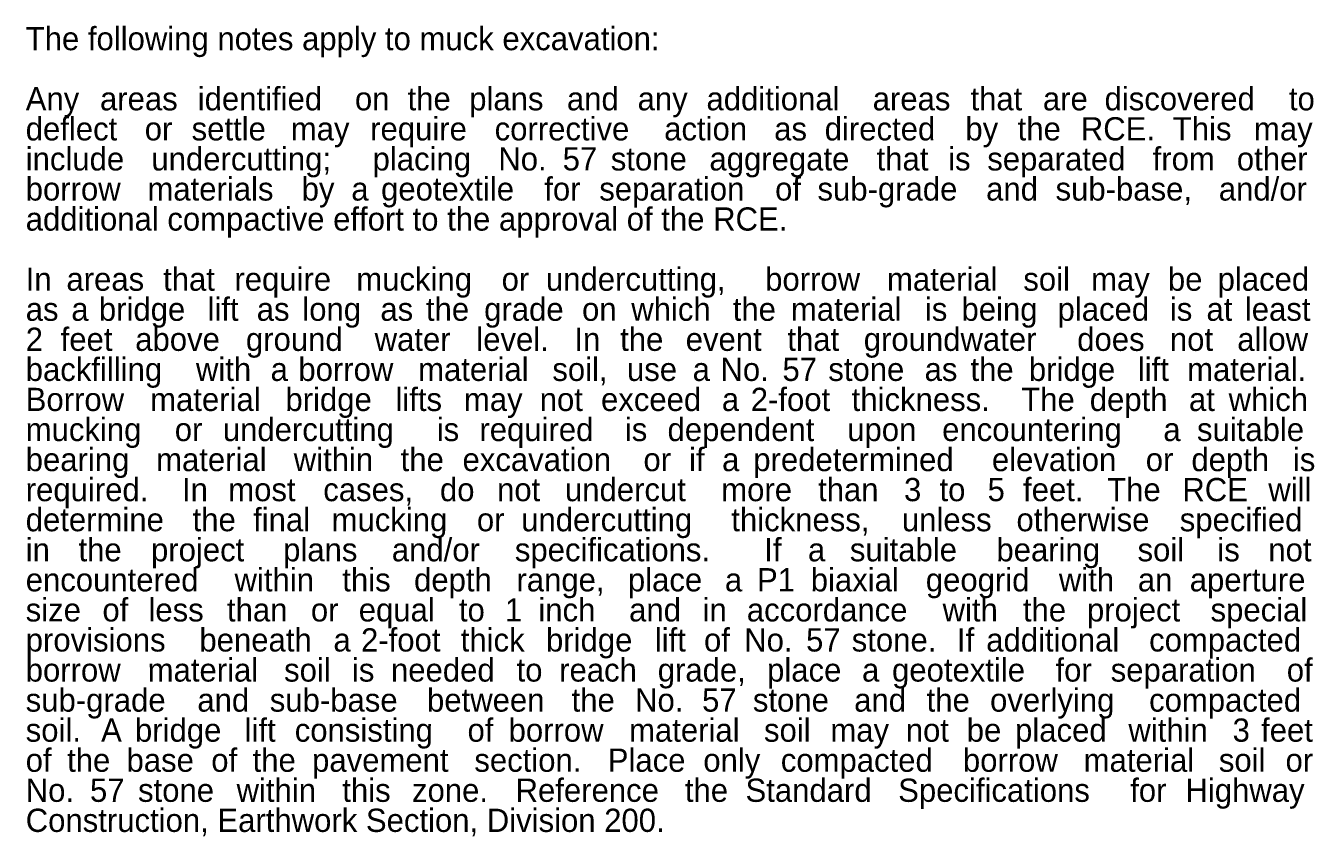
# Model space of a CAD drawing. Extents: x 4804 to 5434, y 4929 to 5221.
# Drawn here: x 5363.1 to 5432.9, y 5158.8 to 5202.8 of the extents above; entities that cross this region are included whole.
import ezdxf

# ---------------------------------------------------------------- set-up
doc = ezdxf.new("R2010")
doc.units = 0
doc.layers.add('RD_TX_RoadID', color=7, linetype='Continuous')

msp = doc.modelspace()

# ---------------------------------------------------------------- texts
at = {"layer": 'RD_TX_RoadID'}
for s, height, p in [('The following notes apply to muck excavation:', 1.25864, (5363.131, 5201.428)), ('Any ', 1.2586, (5363.131, 5198.17)), ('identified ', 1.25864, (5372.45, 5198.17)), ('the ', 1.2586, (5383.817, 5198.17)), ('plans ', 1.2586, (5387.155, 5198.17)), ('and ', 1.2586, (5392.449, 5198.17)), ('additional ', 1.25864, (5400.009, 5198.17)), ('that ', 1.2586, (5414.309, 5198.17)), ('discovered ', 1.25864, (5421.574, 5198.17)), ('to ', 1.2586, (5431.559, 5198.17)), ('areas ', 1.2586, (5367.155, 5198.17)), ('on ', 1.2586, (5380.966, 5198.17)), ('any ', 1.2586, (5396.278, 5198.17)), ('areas ', 1.2586, (5409.013, 5198.17)), ('are ', 1.2586, (5418.233, 5198.17)), ('deflect ', 1.2586, (5363.131, 5196.541)), ('settle ', 1.2586, (5372.118, 5196.541)), ('require ', 1.2586, (5381.791, 5196.541)), ('corrective ', 1.25864, (5388.533, 5196.541)), ('action ', 1.2586, (5397.718, 5196.541)), ('directed ', 1.2586, (5406.413, 5196.541)), ('by ', 1.2586, (5414.034, 5196.541)), ('the ', 1.2586, (5416.867, 5196.541)), ('RCE. ', 1.2586, (5420.286, 5196.541)), ('This ', 1.2586, (5425.269, 5196.541)), ('or ', 1.2586, (5369.578, 5196.541)), ('may ', 1.2586, (5377.491, 5196.541)), ('as ', 1.2586, (5403.677, 5196.541)), ('may ', 1.2586, (5429.666, 5196.541)), ('include ', 1.2586, (5363.131, 5194.912)), ('undercutting; ', 1.25864, (5369.939, 5194.912)), ('placing ', 1.2586, (5381.922, 5194.912)), ('No. ', 1.2586, (5388.731, 5194.912)), ('57 ', 1.2586, (5392.217, 5194.912)), ('stone ', 1.2586, (5394.825, 5194.912)), ('aggregate ', 1.2586, (5400.168, 5194.912)), ('that ', 1.2586, (5409.224, 5194.912)), ('is ', 1.2586, (5413.1, 5194.912)), ('separated ', 1.2586, (5415.219, 5194.912)), ('from ', 1.2586, (5424.178, 5194.912)), ('other ', 1.2586, (5428.739, 5194.912)), ('borrow ', 1.2586, (5363.131, 5193.283)), ('materials ', 1.2586, (5369.725, 5193.283)), ('by ', 1.2586, (5378.08, 5193.283)), ('geotextile ', 1.25864, (5382.381, 5193.283)), ('for ', 1.2586, (5391.222, 5193.283)), ('separation ', 1.25864, (5394.201, 5193.283)), ('of ', 1.2586, (5403.727, 5193.283)), ('sub-grade ', 1.2586, (5406.022, 5193.283)), ('and ', 1.2586, (5415.157, 5193.283)), ('sub-base, ', 1.2586, (5418.919, 5193.283)), ('and/or ', 1.2586, (5427.761, 5193.283)), ('a ', 1.2586, (5380.768, 5193.283)), ('additional compactive effort to the approval of the RCE. ', 1.25864, (5363.131, 5191.654)), ('In ', 1.2586, (5363.131, 5188.396)), ('that ', 1.2586, (5370.572, 5188.396)), ('require ', 1.2586, (5374.436, 5188.396)), ('mucking ', 1.2586, (5381.039, 5188.396)), ('undercutting, ', 1.25864, (5391.312, 5188.396)), ('borrow ', 1.2586, (5403.187, 5188.396)), ('material ', 1.2586, (5409.788, 5188.396)), ('soil ', 1.2586, (5417.172, 5188.396)), ('be ', 1.2586, (5425.004, 5188.396)), ('placed ', 1.2586, (5427.698, 5188.396)), ('areas ', 1.2586, (5365.336, 5188.396)), ('or ', 1.2586, (5388.911, 5188.396)), ('may ', 1.2586, (5420.843, 5188.396)), ('bridge ', 1.2586, (5367.094, 5186.767)), ('lift ', 1.2586, (5372.983, 5186.767)), ('long ', 1.2586, (5378.115, 5186.767)), ('the ', 1.2586, (5384.813, 5186.767)), ('grade ', 1.2586, (5387.966, 5186.767)), ('which ', 1.2586, (5395.933, 5186.767)), ('the ', 1.2586, (5401.431, 5186.767)), ('material ', 1.2586, (5404.584, 5186.767)), ('is ', 1.2586, (5411.841, 5186.767)), ('being ', 1.2586, (5413.823, 5186.767)), ('placed ', 1.2586, (5419.027, 5186.767)), ('is ', 1.2586, (5425.112, 5186.767)), ('least ', 1.2586, (5429.172, 5186.767)), ('as ', 1.2586, (5363.131, 5186.767)), ('a ', 1.2586, (5365.601, 5186.767)), ('as ', 1.2586, (5375.645, 5186.767)), ('as ', 1.2586, (5382.342, 5186.767)), ('on ', 1.2586, (5393.269, 5186.767)), ('at ', 1.2586, (5427.094, 5186.767)), ('2 ', 1.2586, (5363.131, 5185.138)), ('feet ', 1.2586, (5365.024, 5185.138)), ('above ', 1.2586, (5369.064, 5185.138)), ('ground ', 1.2586, (5375.061, 5185.138)), ('water ', 1.2586, (5382.033, 5185.138)), ('level. ', 1.2586, (5387.54, 5185.138)), ('In ', 1.2586, (5392.853, 5185.138)), ('the ', 1.2586, (5395.331, 5185.138)), ('event ', 1.2586, (5398.883, 5185.138)), ('that ', 1.2586, (5404.391, 5185.138)), ('groundwater ', 1.25864, (5408.529, 5185.138)), ('does ', 1.2586, (5420.092, 5185.138)), ('not ', 1.2586, (5425.112, 5185.138)), ('allow ', 1.2586, (5428.761, 5185.138)), ('backfilling ', 1.25864, (5363.131, 5183.509)), ('with ', 1.2586, (5372.353, 5183.509)), ('borrow ', 1.2586, (5377.901, 5183.509)), ('material ', 1.2586, (5384.388, 5183.509)), ('soil, ', 1.2586, (5391.658, 5183.509)), ('No. ', 1.2586, (5400.765, 5183.509)), ('57 ', 1.2586, (5404.125, 5183.509)), ('stone ', 1.2586, (5406.608, 5183.509)), ('the ', 1.2586, (5414.307, 5183.509)), ('bridge ', 1.2586, (5417.472, 5183.509)), ('lift ', 1.2586, (5423.373, 5183.509)), ('material. ', 1.2586, (5426.047, 5183.509)), ('a ', 1.2586, (5376.396, 5183.509)), ('use ', 1.2586, (5395.702, 5183.509)), ('a ', 1.2586, (5399.259, 5183.509)), ('as ', 1.2586, (5411.824, 5183.509)), ('Borrow ', 1.2586, (5363.131, 5181.88)), ('material ', 1.2586, (5369.872, 5181.88)), ('bridge ', 1.2586, (5377.2, 5181.88)), ('lifts ', 1.2586, (5383.159, 5181.88)), ('exceed ', 1.2586, (5394.295, 5181.88)), ('2-foot ', 1.2586, (5402.407, 5181.88)), ('thickness. ', 1.25864, (5407.875, 5181.88)), ('The ', 1.2586, (5417.059, 5181.88)), ('depth ', 1.2586, (5420.772, 5181.88)), ('which ', 1.2586, (5428.293, 5181.88)), ('may ', 1.2586, (5386.87, 5181.88)), ('not ', 1.2586, (5390.975, 5181.88)), ('a ', 1.2586, (5400.843, 5181.88)), ('at ', 1.2586, (5426.144, 5181.88)), ('mucking ', 1.2586, (5363.131, 5180.251)), ('or ', 1.2586, (5371.206, 5180.251)), ('undercutting ', 1.25864, (5373.809, 5180.251)), ('is ', 1.2586, (5385.398, 5180.251)), ('required ', 1.2586, (5387.708, 5180.251)), ('is ', 1.2586, (5395.588, 5180.251)), ('dependent ', 1.2586, (5397.898, 5180.251)), ('upon ', 1.2586, (5407.633, 5180.251)), ('encountering ', 1.25864, (5412.775, 5180.251)), ('a ', 1.2586, (5424.756, 5180.251)), ('suitable ', 1.2586, (5426.579, 5180.251)), ('bearing ', 1.2586, (5363.131, 5178.622)), ('material ', 1.2586, (5370.195, 5178.622)), ('within ', 1.2586, (5377.65, 5178.622)), ('the ', 1.2586, (5383.443, 5178.622)), ('excavation ', 1.25864, (5386.793, 5178.622)), ('if ', 1.2586, (5399.066, 5178.622)), ('predetermined ', 1.25864, (5402.544, 5178.622)), ('elevation ', 1.2586, (5415.471, 5178.622)), ('depth ', 1.2586, (5426.277, 5178.622)), ('is ', 1.2586, (5431.776, 5178.622)), ('or ', 1.2586, (5396.594, 5178.622)), ('a ', 1.2586, (5400.853, 5178.622)), ('or ', 1.2586, (5423.805, 5178.622)), ('required. ', 1.2586, (5363.131, 5176.994)), ('In ', 1.2586, (5371.598, 5176.994)), ('do ', 1.2586, (5385.571, 5176.994)), ('undercut ', 1.2586, (5392.343, 5176.994)), ('than ', 1.2586, (5406.053, 5176.994)), ('3 ', 1.2586, (5410.709, 5176.994)), ('5 ', 1.2586, (5415.235, 5176.994)), ('feet. ', 1.2586, (5417.157, 5176.994)), ('The ', 1.2586, (5421.715, 5176.994)), ('RCE ', 1.2586, (5425.786, 5176.994)), ('will ', 1.2586, (5430.444, 5176.994)), ('most ', 1.2586, (5374.105, 5176.994)), ('cases, ', 1.2586, (5379.25, 5176.994)), ('not ', 1.2586, (5388.664, 5176.994)), ('more ', 1.2586, (5400.809, 5176.994)), ('to ', 1.2586, (5412.631, 5176.994)), ('determine ', 1.2586, (5363.131, 5175.365)), ('the ', 1.2586, (5372.173, 5175.365)), ('final ', 1.2586, (5375.449, 5175.365)), ('mucking ', 1.2586, (5379.702, 5175.365)), ('or ', 1.2586, (5387.572, 5175.365)), ('undercutting ', 1.25864, (5389.97, 5175.365)), ('thickness, ', 1.25864, (5401.354, 5175.365)), ('unless ', 1.2586, (5410.592, 5175.365)), ('otherwise ', 1.2586, (5416.801, 5175.365)), ('specified ', 1.2586, (5425.647, 5175.365)), ('in ', 1.2586, (5363.131, 5173.736)), ('the ', 1.2586, (5365.988, 5173.736)), ('project ', 1.2586, (5369.92, 5173.736)), ('plans ', 1.2586, (5377.076, 5173.736)), ('and/or ', 1.2586, (5382.963, 5173.736)), ('specifications. ', 1.25864, (5389.63, 5173.736)), ('If ', 1.2586, (5403.137, 5173.736)), ('suitable ', 1.2586, (5407.777, 5173.736)), ('bearing ', 1.2586, (5415.715, 5173.736)), ('soil ', 1.2586, (5423.36, 5173.736)), ('is ', 1.2586, (5427.683, 5173.736)), ('not ', 1.2586, (5430.444, 5173.736)), ('a ', 1.2586, (5405.505, 5173.736)), ('encountered ', 1.25864, (5363.131, 5172.107)), ('within ', 1.2586, (5374.443, 5172.107)), ('this ', 1.2586, (5380.282, 5172.107)), ('depth ', 1.2586, (5384.168, 5172.107)), ('place ', 1.2586, (5395.752, 5172.107)), ('P1 ', 1.2586, (5402.746, 5172.107)), ('biaxial ', 1.2586, (5405.657, 5172.107)), ('geogrid ', 1.2586, (5411.89, 5172.107)), ('with ', 1.2586, (5419.098, 5172.107)), ('range, ', 1.2586, (5389.715, 5172.107)), ('a ', 1.2586, (5401.008, 5172.107)), ('an ', 1.2586, (5423.375, 5172.107)), ('aperture ', 1.2586, (5426.187, 5172.107)), ('size ', 1.2586, (5363.131, 5170.478)), ('of ', 1.2586, (5367.287, 5170.478)), ('less ', 1.2586, (5369.78, 5170.478)), ('than ', 1.2586, (5374.035, 5170.478)), ('or ', 1.2586, (5378.58, 5170.478)), ('equal ', 1.2586, (5381.172, 5170.478)), ('to ', 1.2586, (5386.598, 5170.478)), ('1 ', 1.2586, (5389.091, 5170.478)), ('inch ', 1.2586, (5390.902, 5170.478)), (' and ', 1.2586, (5395.35, 5170.478)), ('in ', 1.2586, (5399.798, 5170.478)), ('accordance ', 1.25864, (5402.194, 5170.478)), ('with ', 1.2586, (5412.8, 5170.478)), ('the ', 1.2586, (5417.15, 5170.478)), ('project ', 1.2586, (5420.62, 5170.478)), ('special ', 1.2586, (5427.315, 5170.478)), ('provisions ', 1.25864, (5363.131, 5168.849)), ('beneath ', 1.2586, (5372.54, 5168.849)), ('2-foot ', 1.2586, (5381.295, 5168.849)), ('thick ', 1.2586, (5386.696, 5168.849)), ('bridge ', 1.2586, (5391.317, 5168.849)), ('lift ', 1.2586, (5397.209, 5168.849)), ('of ', 1.2586, (5399.874, 5168.849)), ('No. ', 1.2586, (5402.052, 5168.849)), ('57 ', 1.2586, (5405.403, 5168.849)), ('stone. ', 1.2586, (5407.877, 5168.849)), ('If ', 1.2586, (5413.572, 5168.849)), ('additional ', 1.25864, (5415.164, 5168.849)), ('compacted ', 1.2586, (5423.986, 5168.849)), ('a ', 1.2586, (5379.8, 5168.849)), ('borrow ', 1.2586, (5363.131, 5167.22)), ('material ', 1.2586, (5369.738, 5167.22)), ('soil ', 1.2586, (5377.128, 5167.22)), ('is ', 1.2586, (5380.804, 5167.22)), ('needed ', 1.2586, (5382.918, 5167.22)), ('reach ', 1.2586, (5392.029, 5167.22)), ('grade, ', 1.2586, (5397.368, 5167.22)), ('place ', 1.2586, (5403.292, 5167.22)), ('geotextile ', 1.25864, (5410.06, 5167.22)), ('for ', 1.2586, (5418.914, 5167.22)), ('separation ', 1.25864, (5421.905, 5167.22)), ('of ', 1.2586, (5431.444, 5167.22)), ('to ', 1.2586, (5389.721, 5167.22)), ('a ', 1.2586, (5408.435, 5167.22)), ('sub-grade ', 1.2586, (5363.131, 5165.591)), ('and ', 1.2586, (5372.429, 5165.591)), ('sub-base ', 1.2586, (5376.353, 5165.591)), ('between ', 1.2586, (5384.87, 5165.591)), ('the ', 1.2586, (5392.703, 5165.591)), ('No. ', 1.2586, (5396.139, 5165.591)), ('57 ', 1.2586, (5399.77, 5165.591)), ('stone ', 1.2586, (5402.523, 5165.591)), ('and ', 1.2586, (5408.011, 5165.591)), ('the ', 1.2586, (5411.935, 5165.591)), ('overlying ', 1.2586, (5415.371, 5165.591)), ('compacted ', 1.2586, (5423.986, 5165.591)), ('soil. ', 1.2586, (5363.131, 5163.962)), ('A ', 1.2586, (5367.214, 5163.962)), ('bridge ', 1.2586, (5369.051, 5163.962)), ('lift ', 1.2586, (5374.991, 5163.962)), ('consisting ', 1.25864, (5377.705, 5163.962)), ('of ', 1.2586, (5387.064, 5163.962)), ('borrow ', 1.2586, (5389.29, 5163.962)), ('material ', 1.2586, (5395.816, 5163.962)), ('soil ', 1.2586, (5403.125, 5163.962)), ('not ', 1.2586, (5410.806, 5163.962)), ('be ', 1.2586, (5414.107, 5163.962)), ('placed ', 1.2586, (5416.726, 5163.962)), ('within ', 1.2586, (5422.863, 5163.962)), ('3 ', 1.2586, (5428.508, 5163.962)), ('feet ', 1.2586, (5430.052, 5163.962)), ('may ', 1.2586, (5406.721, 5163.962)), ('of ', 1.2586, (5363.131, 5162.333)), ('the ', 1.2586, (5365.373, 5162.333)), ('base ', 1.2586, (5368.592, 5162.333)), ('of ', 1.2586, (5373.182, 5162.333)), ('the ', 1.2586, (5375.424, 5162.333)), ('section. ', 1.2586, (5387.434, 5162.333)), ('Place ', 1.2586, (5394.66, 5162.333)), ('only ', 1.2586, (5399.837, 5162.333)), ('compacted ', 1.2586, (5404.034, 5162.333)), ('borrow ', 1.2586, (5413.899, 5162.333)), ('material ', 1.2586, (5420.441, 5162.333)), ('soil ', 1.2586, (5427.765, 5162.333)), ('pavement ', 1.2586, (5378.644, 5162.333)), ('or ', 1.2586, (5431.376, 5162.333)), ('No. ', 1.2586, (5363.131, 5160.704)), ('57 ', 1.2586, (5366.612, 5160.704)), ('stone ', 1.2586, (5369.216, 5160.704)), ('within ', 1.2586, (5374.554, 5160.704)), ('this ', 1.2586, (5380.282, 5160.704)), ('zone. ', 1.2586, (5384.056, 5160.704)), (' Reference ', 1.25864, (5389.199, 5160.704)), ('the ', 1.2586, (5398.838, 5160.704)), ('Standard ', 1.2586, (5402.124, 5160.704)), ('Specifications ', 1.25864, (5410.393, 5160.704)), ('for ', 1.2586, (5422.962, 5160.704)), ('Highway ', 1.2586, (5425.954, 5160.704)), ('Construction, Earthwork Section, Division 200. ', 1.25864, (5363.131, 5159.075))]:
    msp.add_text(s, height=height, dxfattribs=at).set_placement(p)

doc.saveas('drawing.dxf')
